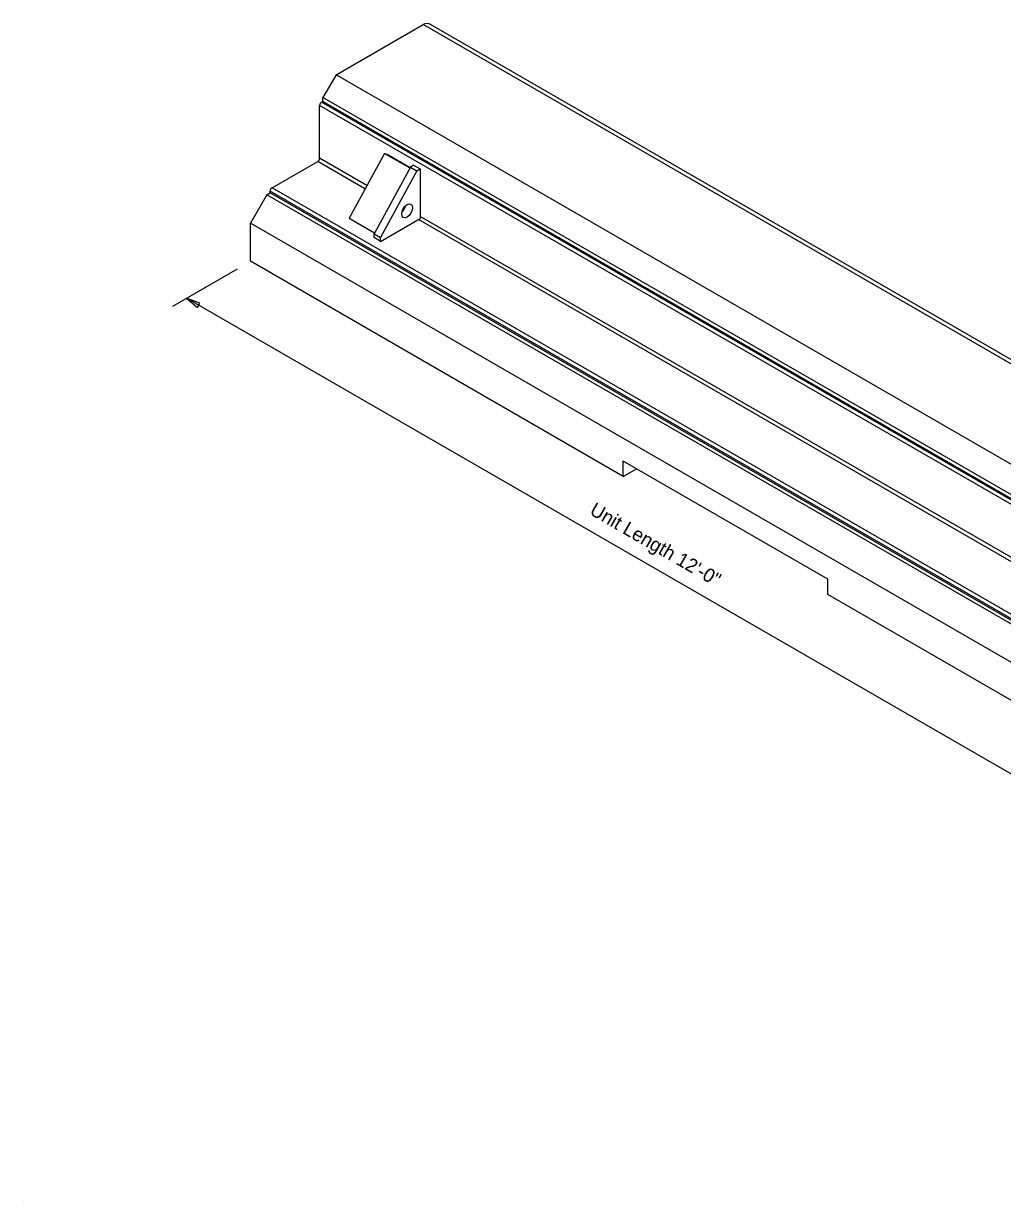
# Model space of a CAD drawing. Extents: x 10000 to 10032.7, y 10000 to 10024.9.
# Drawn here: x 10000 to 10010.71, y 10000 to 10012.9 of the extents above; entities that cross this region are included whole.
import ezdxf

# ---------------------------------------------------------------- set-up
doc = ezdxf.new("R2010")
doc.units = 0
for name, color, linetype in [('Default', 7, 'Continuous'), ('Dimension', 7, 'Continuous'), ('DSText', 7, 'Continuous'), ('Patterning', 7, 'Continuous'), ('PlotBorder_dp', 7, 'Continuous'), ('TextMisc', 7, 'Continuous')]:
    doc.layers.add(name, color=color, linetype=linetype)

msp = doc.modelspace()

# ---------------------------------------------------------------- linework, layer by layer
at = {"layer": 'Default'}
for p, q in [((10001.632, 10009.808), (10002.338, 10010.216)), ((10012.173, 10003.894), (10001.781, 10009.894))]:
    msp.add_line(p, q, dxfattribs=at)
at = {"layer": 'Dimension'}
msp.add_lwpolyline([(10001.781, 10009.894), (10001.903, 10009.793), (10001.929, 10009.839)], close=True, dxfattribs=at)
at = {"layer": 'Patterning'}
msp.add_line((10000, 10000), (10000, 10000), dxfattribs=at)
msp.add_line((10000, 10000), (10000, 10000), dxfattribs=at)
at = {"layer": 'PlotBorder_dp'}
for p, q in [((10013.63, 10006.003), (10003.238, 10012.003)), ((10013.651, 10006.039), (10003.259, 10012.039)), ((10003.948, 10011.479), (10003.562, 10010.769)), ((10003.948, 10011.479), (10004.225, 10011.319)), ((10003.948, 10011.479), (10003.976, 10011.469)), ((10003.976, 10011.469), (10004.227, 10011.324)), ((10003.733, 10011.092), (10003.217, 10011.39)), ((10003.753, 10011.128), (10003.238, 10011.426)), ((10004.23, 10011.329), (10003.833, 10010.6)), ((10004.266, 10011.35), (10004.23, 10011.329)), ((10004.23, 10011.329), (10004.302, 10011.287)), ((10004.266, 10011.35), (10004.338, 10011.308)), ((10004.302, 10011.287), (10003.905, 10010.558)), ((10004.302, 10011.287), (10004.338, 10011.308)), ((10004.338, 10011.308), (10004.338, 10010.766)), ((10013.11, 10005.101), (10002.718, 10011.101)), ((10013.089, 10005.065), (10002.697, 10011.065)), ((10003.562, 10010.769), (10003.839, 10010.609)), ((10003.905, 10010.516), (10004.338, 10010.766)), ((10013.016, 10005.732), (10004.318, 10010.754)), ((10013.036, 10005.769), (10004.338, 10010.79)), ((10003.833, 10010.558), (10003.833, 10010.6)), ((10003.833, 10010.6), (10003.905, 10010.558)), ((10003.905, 10010.516), (10003.833, 10010.558)), ((10003.905, 10010.516), (10003.905, 10010.558))]:
    msp.add_line(p, q, dxfattribs=at)
msp.add_ellipse((10004.194, 10010.85), major_axis=(0.0415, 0.0718), ratio=0.57735, dxfattribs=at)
msp.add_ellipse((10004.122, 10010.891), major_axis=(0.0415, 0.0718), ratio=0.57735, start_param=4.198058, end_param=5.223723, dxfattribs=at)
at = {"layer": 'TextMisc'}
for p, q in [((10003.418, 10012.339), (10004.369, 10012.888)), ((10014.761, 10006.888), (10004.369, 10012.888)), ((10014.888, 10006.863), (10004.452, 10012.888)), ((10003.418, 10012.339), (10003.274, 10012.089)), ((10013.811, 10006.339), (10003.418, 10012.339)), ((10003.238, 10011.426), (10003.238, 10012.003)), ((10003.259, 10012.039), (10003.274, 10012.047)), ((10013.666, 10006.089), (10003.274, 10012.089)), ((10003.274, 10012.047), (10003.274, 10012.089)), ((10013.666, 10006.048), (10003.274, 10012.047)), ((10002.718, 10011.101), (10003.217, 10011.39)), ((10002.661, 10011.027), (10002.48, 10010.714)), ((10002.661, 10011.027), (10002.697, 10011.048)), ((10013.053, 10005.027), (10002.661, 10011.027)), ((10002.697, 10011.048), (10002.697, 10011.065)), ((10013.089, 10005.048), (10002.697, 10011.048)), ((10012.872, 10004.714), (10002.48, 10010.714)), ((10002.48, 10010.298), (10002.48, 10010.714)), ((10006.558, 10007.943), (10002.48, 10010.298)), ((10006.558, 10007.943), (10006.558, 10008.11)), ((10008.795, 10006.818), (10006.558, 10008.11)), ((10006.558, 10007.943), (10006.702, 10008.027)), ((10008.795, 10006.652), (10008.795, 10006.818)), ((10012.872, 10004.298), (10008.795, 10006.652))]:
    msp.add_line(p, q, dxfattribs=at)
for centre, radius, start, end in [((10004.411, 10012.816), 0.0833, 59.9631, 120), ((10003.28, 10012.003), 0.0417, 120, 180), ((10003.196, 10011.426), 0.0417, 300, 0), ((10002.738, 10011.065), 0.0417, 120, 180)]:
    msp.add_arc(centre, radius, start, end, dxfattribs=at)

# ---------------------------------------------------------------- texts
at = {"layer": 'DSText'}
msp.add_text('Unit Length 12\'-0"', height=0.1512, rotation=330, dxfattribs=at).set_placement((10006.18, 10007.536))

doc.saveas('drawing.dxf')
